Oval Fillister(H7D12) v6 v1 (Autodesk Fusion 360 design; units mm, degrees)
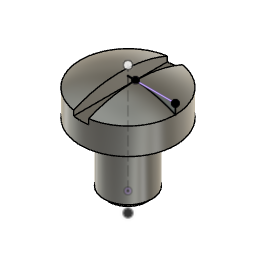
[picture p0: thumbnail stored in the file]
sketch "Sketch1" plane through (0, 0, 0) normal (0, 1, 0) x axis (1, 0, 0)
  line L1 (0, -12.6) -> (0, 0)
  line L2 (-6, -12.6) -> (0, -12.6)
  line L3 (-6, -8) -> (-6, -12.6)
  line L4 (-3, -8) -> (-6, -8)
  line L5 (-3, -0.6) -> (-3, -8)
  line L6 (-14.2312, 0) -> (0, 0)
  line L7 (-2.4, 0) -> (0, 0)
  line L8 (-2.4, 0) -> (-3, -0.6)
  point P1 (0, 0)
  point P2 (0, 0)
  point P8 (0, 0)
  point P10 (0, 0)
  point P11 (-2.4, 0)
  point P3 (0, -12.6)
  point P4 (-6, -12.6)
  point P5 (-6, -8)
  point P7 (-3, -0.6)
  coincident P1 P2
  vertical L1
  perpendicular L1 L2
  perpendicular L2 L3
  perpendicular L3 L4
  perpendicular L2 L5
  coincident P1 P8
  perpendicular L1 L6
  coincident P1 P10
  coincident L6 P11
  dimension "d1" distance P3 P4 = 6
  dimension "d2" distance P4 P5 = 4.6
  dimension "d3" distance P1 L4 = 8
  dimension "d4" distance L1 L5 = 3
  dimension "d6" angle L6 L8 = 45
  dimension "d7" distance P7 P11 = 0.6
revolve "Revolve1" sketch "Sketch1" AlongAngle 360
sketch "Sketch2" plane through (0, 0, 0) normal (0, 1, 0) x axis (1, 0, 0)
  line L1 (-0.95, -10.7) -> (0.95, -10.7)
  line L2 (-0.95, -14.5) -> (-0.95, -10.7)
  line L3 (0.95, -14.5) -> (-0.95, -14.5)
  line L4 (0.95, -10.7) -> (0.95, -14.5)
  line L5 (-0.95, -14.5) -> (0.95, -10.7)
  line L6 (0.95, -14.5) -> (-0.95, -10.7)
  line L7 (-6, -12.6) -> (6, -12.6)
  line L8 (0, -15.1803) -> (0, -11.2158)
  point P6 (0, -12.6)
  point P2 (0.95, -10.7)
  point P3 (-0.95, -10.7)
  horizontal L1
  perpendicular L1 L2
  parallel L1 L3
  parallel L2 L4
  coincident L5 P6
  coincident L6 P6
  coincident P6 L7
  midpoint P6 L7
  perpendicular L1 L8
  coincident P6 L8
  dimension "d9" distance L1 L7 = 1.9
  dimension "d10" distance P2 P3 = 1.9
extrude "Extrude1" cut sketch "Sketch2" profile of L1 L2 L3 L4 L7 L8 distance 8.5
sketch "Sketch3" plane through (0, 0, 0) normal (0, 1, 0) x axis (1, 0, 0)
  line L1 (0.95, -12.6) -> (6, -12.6)
  line L2 (6, -11.35) -> (6, -12.6)
  line L3 (0, -13.7981) -> (0, 0)
  line L4 (0, -12.6) -> (0.95, -12.6)
  line L5 (6, -12.6) -> (0.95, -12.6)
  arc A1 centre (0, 2.425) radius 15.025 clockwise from (6, -11.35) to (0, -12.6)
  point P2 (6, -12.6)
  point P4 (6, -12.6)
  point P1 (0, 0)
  point P6 (0, 0)
  point P3 (0.95, -12.6)
  point P8 (0.95, -12.6)
  point P9 (0, -12.6)
  point P10 (6, -12.6)
  point P5 (6, -11.35)
  coincident P2 P4
  perpendicular L1 L2
  coincident P1 P6
  vertical L3
  coincident P3 P8
  coincident L3 P9
  perpendicular L3 L4
  coincident P2 P10
  tangent L4 A1
  dimension "d16" distance P5 P10 = 1.25
revolve "Revolve4" sketch "Sketch3" AlongAngle 360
